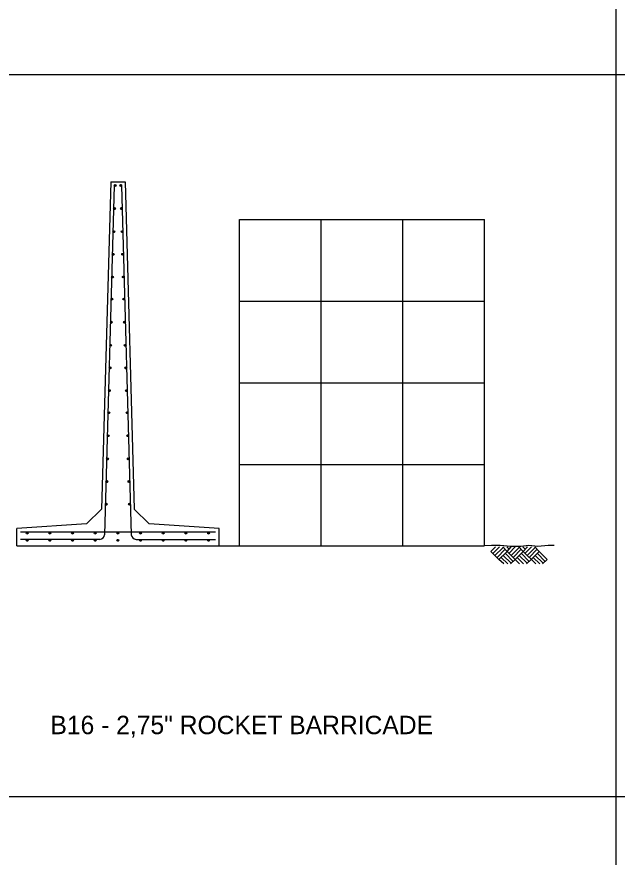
# Model space of a CAD drawing. Extents: x -0.04 to 2.79, y -0.02 to 1.81.
# Drawn here: x 1.7776 to 2.117, y 0.4542 to 0.9292 of the extents above; entities that cross this region are included whole.
import ezdxf

# ---------------------------------------------------------------- set-up
doc = ezdxf.new("R2010")
doc.units = 0
doc.layers.add('Default', color=7, linetype='Continuous')
doc.layers.add('Level 1', color=7, linetype='Continuous')

msp = doc.modelspace()

# ---------------------------------------------------------------- linework, layer by layer
for p, q in [((2.116174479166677, 1.7318499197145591), (2.116174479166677, 0.08028109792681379)), ((0.1165635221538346, 0.8966657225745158), (2.517841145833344, 0.8966657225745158)), ((0.11656352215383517, 0.48847341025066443), (2.517841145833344, 0.48847341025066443))]:
    msp.add_line(p, q)
at = {"layer": 'Default'}
for p, q in [((1.8307116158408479, 0.835914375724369), (1.8255708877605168, 0.650848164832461)), ((1.8326968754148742, 0.833873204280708), (1.8272138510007, 0.6364843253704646)), ((1.8307116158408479, 0.835914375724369), (1.8388763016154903, 0.835914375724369)), ((1.8368910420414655, 0.833873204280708), (1.842374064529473, 0.6364843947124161)), ((1.8388763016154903, 0.835914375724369), (1.8440170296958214, 0.650848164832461)), ((1.9035271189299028, 0.8146300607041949), (2.041937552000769, 0.8146300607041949)), ((1.9035271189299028, 0.7684932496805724), (2.041937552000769, 0.7684932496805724)), ((1.9035271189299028, 0.7223564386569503), (2.041937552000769, 0.7223564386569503)), ((1.9035271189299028, 0.6762196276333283), (2.041937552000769, 0.6762196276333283)), ((1.8255708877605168, 0.650848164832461), (1.8171038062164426, 0.6426834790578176)), ((1.8440170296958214, 0.650848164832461), (1.8524841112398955, 0.6426834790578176)), ((1.8171038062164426, 0.6426834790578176), (1.777641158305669, 0.639961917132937)), ((1.8919467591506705, 0.639961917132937), (1.8524841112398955, 0.6426834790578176)), ((1.777641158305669, 0.6300828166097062), (1.777641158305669, 0.639961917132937)), ((1.8899055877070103, 0.637920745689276), (1.7796823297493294, 0.637920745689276)), ((1.7830087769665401, 0.637920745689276), (1.78402936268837, 0.637920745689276)), ((1.8919467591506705, 0.6300828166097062), (1.8919467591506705, 0.639961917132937)), ((1.777641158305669, 0.6317972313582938), (1.777641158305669, 0.6317972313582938)), ((1.777641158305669, 0.6317972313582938), (1.777641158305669, 0.6317972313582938)), ((1.8244933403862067, 0.6338384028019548), (1.7796823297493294, 0.6338384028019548)), ((1.7830087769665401, 0.6338384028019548), (1.78402936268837, 0.6338384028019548)), ((1.8450945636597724, 0.6338384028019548), (1.8899055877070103, 0.6338384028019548)), ((1.777641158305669, 0.6300828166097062), (2.0418435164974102, 0.6300828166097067))]:
    msp.add_line(p, q, dxfattribs=at)
for centre, radius, start, end in [((1.8244933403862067, 0.6365599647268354), 0.0027215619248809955, 270, 358.4088597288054), ((1.8450945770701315, 0.6365599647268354), 0.002721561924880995, 181.5911402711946, 269.9999999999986)]:
    msp.add_arc(centre, radius, start, end, dxfattribs=at)
at = {"layer": 'Level 1'}
for p, q in [((1.8326991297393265, 0.8338251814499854), (1.8332575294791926, 0.8343835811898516)), ((1.8328005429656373, 0.8335641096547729), (1.8335186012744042, 0.8342821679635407)), ((1.833002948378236, 0.8334040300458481), (1.8336786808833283, 0.8340797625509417)), ((1.8333384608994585, 0.833377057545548), (1.83370565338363, 0.8337442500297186)), ((1.8362494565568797, 0.833377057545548), (1.8358822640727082, 0.8337442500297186)), ((1.8365849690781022, 0.8334040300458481), (1.8359092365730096, 0.8340797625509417)), ((1.8367873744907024, 0.8335641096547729), (1.8360693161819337, 0.8342821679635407)), ((1.8368887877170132, 0.8338251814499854), (1.836330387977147, 0.8343835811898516)), ((1.8323370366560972, 0.8207898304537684), (1.8328954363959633, 0.8213482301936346)), ((1.832438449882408, 0.8205287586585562), (1.8331565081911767, 0.8212468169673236)), ((1.8326408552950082, 0.8203686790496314), (1.8333165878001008, 0.8210444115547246)), ((1.8329763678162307, 0.820341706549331), (1.8333435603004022, 0.8207088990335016)), ((1.8366115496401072, 0.820341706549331), (1.8362443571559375, 0.8207088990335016)), ((1.8369470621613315, 0.8203686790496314), (1.8362713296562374, 0.8210444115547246)), ((1.8371494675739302, 0.8205287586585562), (1.836431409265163, 0.8212468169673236)), ((1.837250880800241, 0.8207898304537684), (1.8366924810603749, 0.8213482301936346)), ((1.9035271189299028, 0.6300828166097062), (1.9035271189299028, 0.8146300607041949)), ((1.9496639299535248, 0.6300828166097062), (1.9496639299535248, 0.8146300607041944)), ((1.995800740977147, 0.6300828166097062), (1.995800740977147, 0.8146300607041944)), ((2.041937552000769, 0.6300828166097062), (2.041937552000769, 0.8146300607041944)), ((1.831974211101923, 0.8077281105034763), (1.8325326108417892, 0.8082865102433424)), ((1.832075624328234, 0.8074670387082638), (1.832793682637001, 0.8081850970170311)), ((1.8322780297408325, 0.8073069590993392), (1.8329537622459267, 0.8079826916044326)), ((1.8326135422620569, 0.8072799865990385), (1.8329807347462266, 0.8076471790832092)), ((1.8369743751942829, 0.8072799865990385), (1.8366071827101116, 0.8076471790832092)), ((1.8373098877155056, 0.8073069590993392), (1.8366341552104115, 0.8079826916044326)), ((1.837512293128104, 0.8074670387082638), (1.8367942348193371, 0.8081850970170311)), ((1.8376137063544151, 0.8077281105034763), (1.8370553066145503, 0.8082865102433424)), ((1.8316189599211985, 0.7949390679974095), (1.8321773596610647, 0.7954974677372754)), ((1.8317203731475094, 0.7946779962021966), (1.832438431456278, 0.7953960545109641)), ((1.8319227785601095, 0.7945179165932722), (1.832598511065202, 0.7951936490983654)), ((1.832258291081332, 0.7944909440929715), (1.832625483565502, 0.7948581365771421)), ((1.8373296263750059, 0.7944909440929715), (1.8369624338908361, 0.7948581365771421)), ((1.8376651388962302, 0.7945179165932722), (1.836989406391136, 0.7951936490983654)), ((1.8378675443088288, 0.7946779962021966), (1.8371494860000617, 0.7953960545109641)), ((1.8379689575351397, 0.7949390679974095), (1.8374105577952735, 0.7954974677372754)), ((1.831261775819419, 0.7820804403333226), (1.8318201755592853, 0.7826388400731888)), ((1.83136318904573, 0.7818193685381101), (1.832081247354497, 0.7825374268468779)), ((1.8315655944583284, 0.7816592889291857), (1.8322413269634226, 0.7823350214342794)), ((1.8319011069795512, 0.7816323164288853), (1.8322682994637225, 0.7819995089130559)), ((1.837686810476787, 0.7816323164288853), (1.8373196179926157, 0.7819995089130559)), ((1.8380223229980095, 0.7816592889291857), (1.8373465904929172, 0.7823350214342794)), ((1.8382247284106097, 0.7818193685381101), (1.8375066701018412, 0.7825374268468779)), ((1.8383261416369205, 0.7820804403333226), (1.8377677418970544, 0.7826388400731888)), ((1.8309152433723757, 0.7696035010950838), (1.831473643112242, 0.7701619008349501)), ((1.8310166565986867, 0.7693424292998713), (1.8317347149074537, 0.7700604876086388)), ((1.8312190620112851, 0.7691823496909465), (1.8318947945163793, 0.7698580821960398)), ((1.8383688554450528, 0.7691823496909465), (1.8376931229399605, 0.7698580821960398)), ((1.8385712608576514, 0.7693424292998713), (1.8378532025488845, 0.7700604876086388)), ((1.8386726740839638, 0.7696035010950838), (1.8381142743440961, 0.7701619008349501)), ((1.831554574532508, 0.7691553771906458), (1.8319217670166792, 0.7695225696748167)), ((1.8380333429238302, 0.7691553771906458), (1.8376661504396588, 0.7695225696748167)), ((1.8305531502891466, 0.7565681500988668), (1.8311115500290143, 0.757126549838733)), ((1.830654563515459, 0.7563070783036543), (1.8313726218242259, 0.7570251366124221)), ((1.8308569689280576, 0.7561469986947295), (1.83153270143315, 0.7568227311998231)), ((1.8311924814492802, 0.7561200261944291), (1.8315596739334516, 0.7564872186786)), ((1.838395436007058, 0.7561200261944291), (1.838028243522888, 0.7564872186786)), ((1.8387309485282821, 0.7561469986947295), (1.838055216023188, 0.7568227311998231)), ((1.8389333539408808, 0.7563070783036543), (1.838215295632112, 0.7570251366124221)), ((1.8390347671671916, 0.7565681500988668), (1.8384763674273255, 0.757126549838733)), ((1.8301903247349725, 0.7435064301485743), (1.8307487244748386, 0.7440648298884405)), ((1.8302917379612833, 0.7432453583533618), (1.8310097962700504, 0.7439634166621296)), ((1.830494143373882, 0.743085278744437), (1.831169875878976, 0.7437610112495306)), ((1.830829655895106, 0.7430583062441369), (1.831196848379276, 0.7434254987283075)), ((1.8387582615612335, 0.7430583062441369), (1.8383910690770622, 0.7434254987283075)), ((1.8390937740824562, 0.743085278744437), (1.8384180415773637, 0.7437610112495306)), ((1.8392961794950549, 0.7432453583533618), (1.8385781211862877, 0.7439634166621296)), ((1.8393975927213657, 0.7435064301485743), (1.8388391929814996, 0.7440648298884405)), ((1.829835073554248, 0.7307173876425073), (1.830393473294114, 0.7312757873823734)), ((1.8299364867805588, 0.7304563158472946), (1.8306545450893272, 0.7311743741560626)), ((1.830138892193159, 0.7302962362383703), (1.8308146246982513, 0.7309719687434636)), ((1.8304744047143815, 0.7302692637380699), (1.830841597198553, 0.7306364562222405)), ((1.8391135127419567, 0.7302692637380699), (1.8387463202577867, 0.7306364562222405)), ((1.8394490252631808, 0.7302962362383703), (1.8387732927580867, 0.7309719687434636)), ((1.8396514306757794, 0.7304563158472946), (1.8389333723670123, 0.7311743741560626)), ((1.8397528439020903, 0.7307173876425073), (1.839194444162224, 0.7312757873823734)), ((1.8294778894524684, 0.7178587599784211), (1.8300362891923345, 0.7184171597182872)), ((1.8295793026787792, 0.7175976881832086), (1.8302973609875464, 0.7183157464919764)), ((1.8297817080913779, 0.7174376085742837), (1.830457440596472, 0.718113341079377)), ((1.8301172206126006, 0.7174106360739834), (1.830484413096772, 0.717777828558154)), ((1.8394706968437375, 0.7174106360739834), (1.8391035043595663, 0.717777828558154)), ((1.8398062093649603, 0.7174376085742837), (1.8391304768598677, 0.718113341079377)), ((1.840008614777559, 0.7175976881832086), (1.8392905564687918, 0.7183157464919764)), ((1.8401100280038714, 0.7178587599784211), (1.839551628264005, 0.7184171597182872)), ((1.8291313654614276, 0.7053838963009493), (1.8296897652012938, 0.7059422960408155)), ((1.8292327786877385, 0.7051228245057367), (1.8299508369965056, 0.7058408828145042)), ((1.8294351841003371, 0.7049627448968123), (1.8301109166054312, 0.7056384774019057)), ((1.8297706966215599, 0.7049357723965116), (1.8301378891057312, 0.7053029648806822)), ((1.8398172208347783, 0.7049357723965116), (1.839450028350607, 0.7053029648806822)), ((1.840152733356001, 0.7049627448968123), (1.8394770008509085, 0.7056384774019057)), ((1.840355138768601, 0.7051228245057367), (1.8396370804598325, 0.7058408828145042)), ((1.8404565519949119, 0.7053838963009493), (1.8398981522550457, 0.7059422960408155)), ((1.8287692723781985, 0.6923485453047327), (1.8293276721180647, 0.6929069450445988)), ((1.8288706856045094, 0.6920874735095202), (1.8295887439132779, 0.6928055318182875)), ((1.8290730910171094, 0.6919273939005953), (1.829748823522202, 0.6926031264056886)), ((1.8294086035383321, 0.6919004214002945), (1.8297757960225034, 0.6922676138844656)), ((1.840179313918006, 0.6919004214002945), (1.839812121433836, 0.6922676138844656)), ((1.8405148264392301, 0.6919273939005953), (1.8398390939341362, 0.6926031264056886)), ((1.8407172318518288, 0.6920874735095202), (1.8399991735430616, 0.6928055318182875)), ((1.8408186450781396, 0.6923485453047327), (1.8402602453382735, 0.6929069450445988)), ((1.8284064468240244, 0.6792868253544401), (1.8289648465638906, 0.6798452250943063)), ((1.8285078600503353, 0.6790257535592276), (1.8292259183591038, 0.679743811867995)), ((1.828710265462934, 0.6788656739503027), (1.8293859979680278, 0.6795414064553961)), ((1.8408776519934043, 0.6788656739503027), (1.8402019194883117, 0.6795414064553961)), ((1.841080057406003, 0.6790257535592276), (1.8403619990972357, 0.679743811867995)), ((1.8411814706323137, 0.6792868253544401), (1.8406230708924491, 0.6798452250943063)), ((1.829045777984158, 0.6788387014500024), (1.829412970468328, 0.679205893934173)), ((1.8405421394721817, 0.6788387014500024), (1.8401749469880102, 0.679205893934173)), ((1.8280511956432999, 0.666497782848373), (1.828609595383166, 0.6670561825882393)), ((1.8281526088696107, 0.6662367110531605), (1.8288706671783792, 0.6669547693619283)), ((1.8283550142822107, 0.6660766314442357), (1.8290307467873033, 0.666752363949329)), ((1.8286905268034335, 0.6660496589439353), (1.8290577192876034, 0.6664168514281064)), ((1.8408973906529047, 0.6660496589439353), (1.8405301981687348, 0.6664168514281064)), ((1.8412329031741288, 0.6660766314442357), (1.840557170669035, 0.666752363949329)), ((1.8414353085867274, 0.6662367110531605), (1.8407172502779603, 0.6669547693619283)), ((1.8415367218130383, 0.666497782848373), (1.8409783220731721, 0.6670561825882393)), ((1.8276940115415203, 0.6536391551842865), (1.8282524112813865, 0.6541975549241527)), ((1.8277954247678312, 0.653378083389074), (1.8285134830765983, 0.6540961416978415)), ((1.8279978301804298, 0.6532180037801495), (1.828673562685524, 0.6538937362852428)), ((1.8283333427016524, 0.6531910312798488), (1.8287005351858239, 0.6535582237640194)), ((1.8412545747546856, 0.6531910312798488), (1.8408873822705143, 0.6535582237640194)), ((1.8415900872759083, 0.6532180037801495), (1.8409143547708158, 0.6538937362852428)), ((1.841792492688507, 0.653378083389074), (1.8410744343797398, 0.6540961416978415)), ((1.8418939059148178, 0.6536391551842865), (1.8413355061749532, 0.6541975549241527)), ((1.7830110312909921, 0.6373600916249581), (1.7835694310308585, 0.6379184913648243)), ((1.7831124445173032, 0.6370990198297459), (1.7838305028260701, 0.6378170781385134)), ((1.7833148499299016, 0.6369389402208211), (1.7839905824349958, 0.6376146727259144)), ((1.7836503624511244, 0.6369119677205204), (1.7840175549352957, 0.6372791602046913)), ((1.7958268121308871, 0.6373600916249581), (1.7963852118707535, 0.6379184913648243)), ((1.7959282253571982, 0.6370990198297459), (1.7966462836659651, 0.6378170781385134)), ((1.7961306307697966, 0.6369389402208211), (1.7968063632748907, 0.6376146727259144)), ((1.7964661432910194, 0.6369119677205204), (1.7968333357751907, 0.6372791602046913)), ((1.8086425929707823, 0.6373600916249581), (1.8092009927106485, 0.6379184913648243)), ((1.8087440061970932, 0.6370990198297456), (1.8094620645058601, 0.6378170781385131)), ((1.8089464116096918, 0.6369389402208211), (1.8096221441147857, 0.6376146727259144)), ((1.8092819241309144, 0.6369119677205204), (1.8096491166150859, 0.637279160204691)), ((1.8214583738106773, 0.6373600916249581), (1.8220167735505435, 0.6379184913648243)), ((1.8215597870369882, 0.6370990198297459), (1.8222778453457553, 0.6378170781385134)), ((1.8217621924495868, 0.6369389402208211), (1.8224379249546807, 0.6376146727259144)), ((1.8220977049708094, 0.6369119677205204), (1.8224648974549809, 0.6372791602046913)), ((1.8342741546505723, 0.6373600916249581), (1.8348325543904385, 0.6379184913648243)), ((1.8343755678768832, 0.6370990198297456), (1.8350936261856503, 0.6378170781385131)), ((1.8345779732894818, 0.6369389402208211), (1.835253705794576, 0.6376146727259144)), ((1.8349134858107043, 0.6369119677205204), (1.8352806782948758, 0.637279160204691)), ((1.8470899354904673, 0.6373600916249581), (1.8476483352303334, 0.6379184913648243)), ((1.8471913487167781, 0.6370990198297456), (1.8479094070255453, 0.6378170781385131)), ((1.8473937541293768, 0.6369389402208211), (1.848069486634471, 0.6376146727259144)), ((1.8477292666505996, 0.6369119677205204), (1.8480964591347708, 0.637279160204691)), ((1.8599057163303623, 0.6373600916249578), (1.8604641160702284, 0.6379184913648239)), ((1.8600071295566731, 0.6370990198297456), (1.8607251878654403, 0.6378170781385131)), ((1.8602095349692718, 0.6369389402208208), (1.860885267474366, 0.637614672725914)), ((1.8605450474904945, 0.6369119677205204), (1.8609122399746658, 0.637279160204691)), ((1.8727214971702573, 0.6373600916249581), (1.8732798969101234, 0.6379184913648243)), ((1.8728229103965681, 0.6370990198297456), (1.8735409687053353, 0.6378170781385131)), ((1.8730253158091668, 0.6369389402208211), (1.8737010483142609, 0.6376146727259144)), ((1.8733608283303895, 0.6369119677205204), (1.8737280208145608, 0.637279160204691)), ((1.8855372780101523, 0.6373600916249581), (1.8860956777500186, 0.6379184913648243)), ((1.8856386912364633, 0.6370990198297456), (1.8863567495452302, 0.6378170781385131)), ((1.8858410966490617, 0.6369389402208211), (1.8865168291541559, 0.6376146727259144)), ((1.8861766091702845, 0.6369119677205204), (1.8865438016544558, 0.637279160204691)), ((1.7830110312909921, 0.6332777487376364), (1.7835694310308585, 0.6338361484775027)), ((1.7831124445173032, 0.6330166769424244), (1.7838305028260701, 0.6337347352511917)), ((1.7833148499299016, 0.6328565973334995), (1.7839905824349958, 0.6335323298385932)), ((1.7836503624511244, 0.6328296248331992), (1.7840175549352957, 0.6331968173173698)), ((1.7958268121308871, 0.6332777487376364), (1.7963852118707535, 0.6338361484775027)), ((1.7959282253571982, 0.6330166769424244), (1.7966462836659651, 0.6337347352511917)), ((1.7961306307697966, 0.6328565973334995), (1.7968063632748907, 0.6335323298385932)), ((1.7964661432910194, 0.6328296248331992), (1.7968333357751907, 0.6331968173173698)), ((1.8086425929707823, 0.6332777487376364), (1.8092009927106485, 0.6338361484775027)), ((1.8087440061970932, 0.6330166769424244), (1.8094620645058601, 0.6337347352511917)), ((1.8089464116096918, 0.6328565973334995), (1.8096221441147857, 0.6335323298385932)), ((1.8092819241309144, 0.6328296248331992), (1.8096491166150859, 0.6331968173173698)), ((1.8214583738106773, 0.6332777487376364), (1.8220167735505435, 0.6338361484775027)), ((1.8215597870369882, 0.6330166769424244), (1.8222778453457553, 0.6337347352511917)), ((1.8217621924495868, 0.6328565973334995), (1.8224379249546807, 0.6335323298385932)), ((1.8220977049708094, 0.6328296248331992), (1.8224648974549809, 0.6331968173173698)), ((1.8342741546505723, 0.6332777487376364), (1.8348325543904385, 0.6338361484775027)), ((1.8343755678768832, 0.6330166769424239), (1.8350936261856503, 0.6337347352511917)), ((1.8345779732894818, 0.6328565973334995), (1.835253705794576, 0.6335323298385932)), ((1.8349134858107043, 0.6328296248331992), (1.8352806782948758, 0.6331968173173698)), ((1.8470899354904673, 0.6332777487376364), (1.8476483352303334, 0.6338361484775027)), ((1.8471913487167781, 0.6330166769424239), (1.8479094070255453, 0.6337347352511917)), ((1.8473937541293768, 0.6328565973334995), (1.848069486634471, 0.6335323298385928)), ((1.8477292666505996, 0.6328296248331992), (1.8480964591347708, 0.6331968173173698)), ((1.8599057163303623, 0.6332777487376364), (1.8604641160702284, 0.6338361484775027)), ((1.8600071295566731, 0.6330166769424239), (1.8607251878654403, 0.6337347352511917)), ((1.8602095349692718, 0.6328565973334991), (1.860885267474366, 0.6335323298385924)), ((1.8605450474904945, 0.6328296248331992), (1.8609122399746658, 0.6331968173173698)), ((1.8727214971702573, 0.6332777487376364), (1.8732798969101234, 0.6338361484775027)), ((1.8728229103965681, 0.6330166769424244), (1.8735409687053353, 0.6337347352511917)), ((1.8730253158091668, 0.6328565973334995), (1.8737010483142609, 0.6335323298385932)), ((1.8733608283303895, 0.6328296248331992), (1.8737280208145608, 0.6331968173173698)), ((1.8855372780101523, 0.6332777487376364), (1.8860956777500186, 0.6338361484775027)), ((1.8856386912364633, 0.6330166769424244), (1.8863567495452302, 0.6337347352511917)), ((1.8858410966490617, 0.6328565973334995), (1.8865168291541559, 0.6335323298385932)), ((1.8861766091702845, 0.6328296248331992), (1.8865438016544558, 0.6331968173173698)), ((2.0456920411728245, 0.6270542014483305), (2.0481526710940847, 0.6295148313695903)), ((2.050203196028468, 0.6225430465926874), (2.0456920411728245, 0.6270542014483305)), ((2.046854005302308, 0.6259605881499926), (2.050408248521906, 0.6295148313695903)), ((2.047947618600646, 0.6247986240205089), (2.052527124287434, 0.6293097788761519)), ((2.0491095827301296, 0.6236366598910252), (2.0536207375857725, 0.6282161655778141)), ((2.050203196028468, 0.6225430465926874), (2.054782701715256, 0.6270542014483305)), ((2.054782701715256, 0.6270542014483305), (2.052322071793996, 0.6295148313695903)), ((2.055876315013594, 0.6282161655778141), (2.0545776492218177, 0.6295148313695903)), ((2.054782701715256, 0.6270542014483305), (2.0571749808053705, 0.6295148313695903)), ((2.054782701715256, 0.6270542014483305), (2.0571749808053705, 0.6295148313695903)), ((2.059293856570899, 0.6225430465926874), (2.054782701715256, 0.6270542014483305)), ((2.055876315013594, 0.6259605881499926), (2.059430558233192, 0.6295148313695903)), ((2.0570382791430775, 0.6293097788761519), (2.056833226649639, 0.6295148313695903)), ((2.0570382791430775, 0.6247986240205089), (2.0615494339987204, 0.6293097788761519)), ((2.0581318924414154, 0.6236366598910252), (2.0627113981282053, 0.6282161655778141)), ((2.059293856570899, 0.6225430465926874), (2.063805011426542, 0.6270542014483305)), ((2.063805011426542, 0.6270542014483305), (2.0614127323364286, 0.6295148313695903)), ((2.0649669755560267, 0.6282161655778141), (2.06366830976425, 0.6295148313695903)), ((2.063805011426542, 0.6270542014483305), (2.0662656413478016, 0.6295148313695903)), ((2.063805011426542, 0.6270542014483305), (2.0662656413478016, 0.6295148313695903)), ((2.070981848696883, 0.6199457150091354), (2.063805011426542, 0.6270542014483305)), ((2.0649669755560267, 0.6259605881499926), (2.0685212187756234, 0.6295148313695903)), ((2.0660605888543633, 0.6293097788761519), (2.0659238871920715, 0.6295148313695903)), ((2.0660605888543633, 0.6247986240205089), (2.070640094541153, 0.6293097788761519)), ((2.067222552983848, 0.6236366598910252), (2.0717337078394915, 0.6282161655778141)), ((2.0683845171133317, 0.6225430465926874), (2.0728956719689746, 0.6270542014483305)), ((2.0728956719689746, 0.6270542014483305), (2.070435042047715, 0.6295148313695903)), ((2.0774068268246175, 0.6225430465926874), (2.0728956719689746, 0.6270542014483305)), ((2.052868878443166, 0.6199457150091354), (2.050203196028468, 0.6225430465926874)), ((2.0551244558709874, 0.6199457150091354), (2.051365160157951, 0.6236366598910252)), ((2.0570382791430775, 0.6202874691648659), (2.052527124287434, 0.6247986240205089)), ((2.0581318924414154, 0.6213810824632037), (2.0536207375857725, 0.6259605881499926)), ((2.0566965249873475, 0.6199457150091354), (2.059293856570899, 0.6225430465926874)), ((2.061891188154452, 0.6199457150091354), (2.059293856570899, 0.6225430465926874)), ((2.0641467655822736, 0.6199457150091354), (2.060455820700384, 0.6236366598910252)), ((2.0660605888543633, 0.6202874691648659), (2.0615494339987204, 0.6247986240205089)), ((2.067222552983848, 0.6213810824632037), (2.0627113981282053, 0.6259605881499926)), ((2.0657188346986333, 0.6199457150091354), (2.0683845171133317, 0.6225430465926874)), ((2.0732374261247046, 0.6199457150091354), (2.0694781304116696, 0.6236366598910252)), ((2.075151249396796, 0.6202874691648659), (2.070640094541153, 0.6247986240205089)), ((2.0763132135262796, 0.6213810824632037), (2.0717337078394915, 0.6259605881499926)), ((2.074809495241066, 0.6199457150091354), (2.0774068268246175, 0.6225430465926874))]:
    msp.add_line(p, q, dxfattribs=at)
msp.add_lwpolyline([(2.0814610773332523, 0.6304033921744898), (2.077953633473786, 0.6304033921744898), (2.0722121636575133, 0.6297882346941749), (2.067085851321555, 0.6304033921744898), (2.062574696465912, 0.6297882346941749), (2.056833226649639, 0.6297882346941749), (2.0508183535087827, 0.6304033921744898), (2.0460337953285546, 0.6304033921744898), (2.041937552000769, 0.6300828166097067)], dxfattribs=at)
for centre in [(1.83320950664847, 0.833873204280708), (1.8363784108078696, 0.833873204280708), (1.8328474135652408, 0.8208378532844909), (1.8367405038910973, 0.8208378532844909), (1.8324845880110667, 0.8077761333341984), (1.8371033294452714, 0.8077761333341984), (1.8321293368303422, 0.7949870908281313), (1.837458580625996, 0.7949870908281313), (1.8317721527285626, 0.7821284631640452), (1.8378157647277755, 0.7821284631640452), (1.8314256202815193, 0.769651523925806), (1.8381622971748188, 0.769651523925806), (1.8310635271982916, 0.7566161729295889), (1.838524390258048, 0.7566161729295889), (1.8307007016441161, 0.7435544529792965), (1.838887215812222, 0.7435544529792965), (1.830345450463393, 0.7307654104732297), (1.8392424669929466, 0.7307654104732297), (1.829988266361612, 0.7179067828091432), (1.8395996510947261, 0.7179067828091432), (1.8296417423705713, 0.7054319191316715), (1.8399461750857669, 0.7054319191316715), (1.8292796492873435, 0.6923965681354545), (1.840308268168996, 0.6923965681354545), (1.828916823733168, 0.6793348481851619), (1.84067109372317, 0.6793348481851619), (1.828561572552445, 0.6665458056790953), (1.8410263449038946, 0.6665458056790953), (1.828204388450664, 0.6536871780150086), (1.8413835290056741, 0.6536871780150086), (1.7835214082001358, 0.6374081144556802), (1.7963371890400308, 0.6374081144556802), (1.8091529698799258, 0.6374081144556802), (1.821968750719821, 0.6374081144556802), (1.834784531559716, 0.6374081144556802), (1.847600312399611, 0.6374081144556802), (1.860416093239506, 0.6374081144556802), (1.873231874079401, 0.6374081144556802), (1.886047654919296, 0.6374081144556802), (1.7835214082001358, 0.633325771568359), (1.7963371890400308, 0.633325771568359), (1.8091529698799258, 0.633325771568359), (1.821968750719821, 0.633325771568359), (1.834784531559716, 0.633325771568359), (1.847600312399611, 0.633325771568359), (1.860416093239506, 0.633325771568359), (1.873231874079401, 0.633325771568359), (1.886047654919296, 0.633325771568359)]:
    msp.add_circle(centre, 0.0005126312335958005, dxfattribs=at)

# ---------------------------------------------------------------- texts
msp.add_text('B16 - 2,75" ROCKET BARRICADE', height=0.010416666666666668).set_placement((1.7966471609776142, 0.5237134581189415))

doc.saveas('drawing.dxf')
